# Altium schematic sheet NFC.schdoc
size 297 x 209 mm; Symbol: Drawing-Symbol_A4; @Project Name: Hưhwwuey; @Page Count: 8; @Update Date: 2026-10-18; @Create Date: 2026-10-18; @Schematic Name: Schematic1; @Page No: 8; @Page Name: P1; Company: EasyEDA.com; Version: V1.0; Page Size: A4; Device: Drawing-Symbol_A4; @Create Time: 16:45:31; @Update Time: 16:45:31; Border: 1; Width: 1170; Height: 825; Region Start: 1; X Region Count: 6; Y Region Count: 4; Blade Width: 10; Title Block Position: 3; @Board Name: Board1
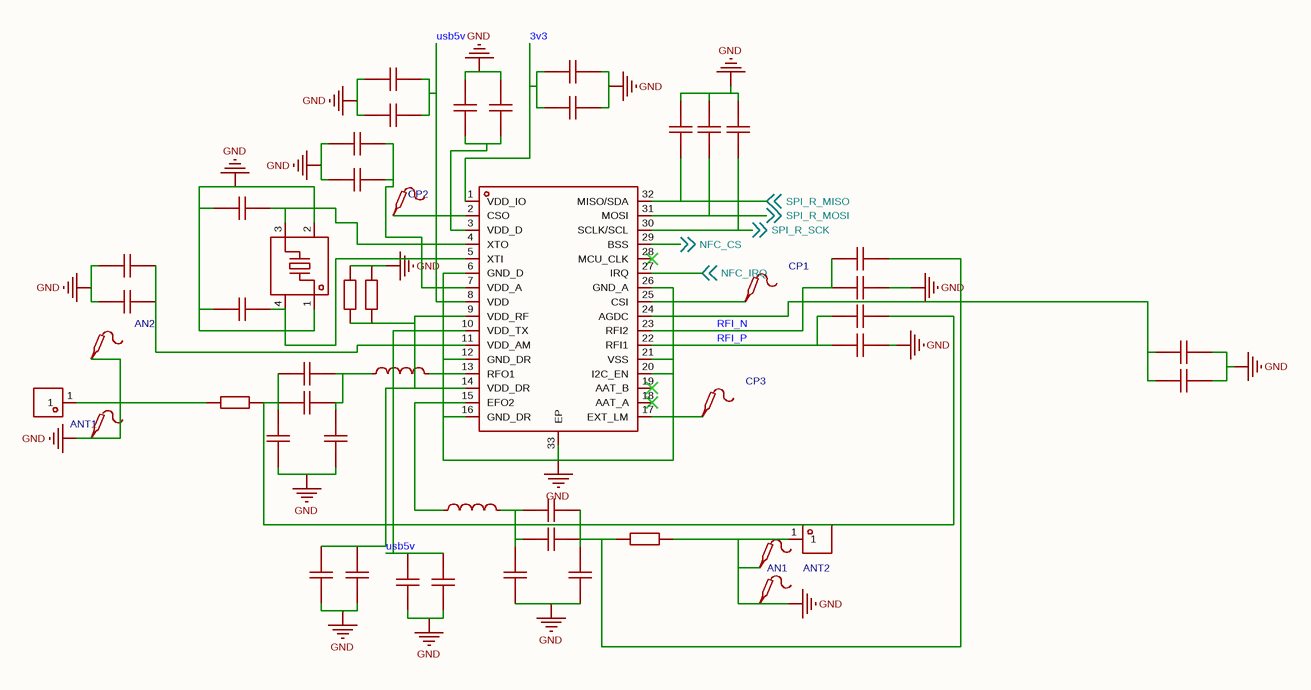
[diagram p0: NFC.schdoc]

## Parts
C91  DNP  [C0402]  (value not drawn)
C92  DNP  [C0402]  (value not drawn)
C93  DNP  [C0402]  (value not drawn)
C94  6pF  [C0402]  (value not drawn)
C95  6pF  [C0402]  (value not drawn)
C96  100pF  [C0402]  (value not drawn)
C97  10pF  [C0402]  (value not drawn)
C98  DNP  [C0402]  (value not drawn)
C99  100pF  [C0402]  (value not drawn)
C100  680pF  [C0402]  (value not drawn)
C101  62pF  [C0402]  (value not drawn)
C102  100pF  [C0402]  (value not drawn)
C103  DNP  [C0402]  (value not drawn)
C104  680pF  [C0402]  (value not drawn)
C105  62pF  [C0402]  (value not drawn)
C106  10pF  [C0402]  (value not drawn)
C107  100pF  [C0402]  (value not drawn)
C108  1uF  [C0402]  (value not drawn)
C109  10nF  [C0402]  (value not drawn)
C110  10nF  [C0402]  (value not drawn)
C111  2.2uF  [C0402]  (value not drawn)
C112  10nF  [C0402]  (value not drawn)
C113  2.2uF  [C0402]  (value not drawn)
C114  10nF  [C0402]  (value not drawn)
C115  2.2uF  [C0402]  (value not drawn)
C116  10nF  [C0402]  (value not drawn)
C117  2.2uF  [C0402]  (value not drawn)
C118  10nF  [C0402]  (value not drawn)
C119  2.2uF  [C0402]  (value not drawn)
C120  10nF  [C0402]  (value not drawn)
C121  2.2uF  [C0402]  (value not drawn)
C122  10nF  [C0402]  (value not drawn)
C123  2.2uF  [C0402]  (value not drawn)
CN4  YTC1P-3515-M20  [CONN-SMD_YTC1P-3515-M20]  (value not drawn)
CN5  YTC1P-3515-M20  [CONN-SMD_YTC1P-3515-M20]  (value not drawn)
L14  270nH  [L0201-RD]  (value not drawn)
L15  270nH  [L0201-RD]  (value not drawn)
R85  0Ω  [R0402]  (value not drawn)
R86  0Ω  [R0402]  (value not drawn)
R87  DNP  [R0402]  (value not drawn)
R88  DNP  [R0402]  (value not drawn)
TP26  CP1  [Test-Point-0.5mm]
TP27  CP2  [Test-Point-0.5mm]
TP28  AN2  [Test-Point-0.5mm]
TP29  ANT1  [Test-Point-0.5mm]
TP30  AN1  [Test-Point-0.5mm]
TP31  ANT2  [Test-Point-0.5mm]
TP32  CP3  [Test-Point-0.5mm]
U49  27.12MHz  [VFQFPN-32_L5.0-W5.0-P0.50-TL-EP3.5]  (value not drawn)
X4  27.12MHz  [CRYSTAL-SMD_4P-L2.0-W1.6-BL-B]  (value not drawn)

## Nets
GND: C91.1 C92.1 C93.1 C94.1 C95.1 C99.2 C100.1 C101.2 C104.1 C105.2 C107.2 C108.1 C109.2 C110.1 C111.1 C112.1 C113.1 C114.1 C115.1 C116.1 C117.1 C118.1 C119.1 C120.1 C121.1 C122.1 C123.1 CN4.1 CN5.1 R85.1 R86.2 R87.2 R88.2 TP28.1 TP29.1 TP30.1 TP31.1 U49.6(GND_D) U49.12(GND_DR) U49.16(GND_DR) U49.20(I2C_EN) U49.21(VSS) U49.26(GND_A) U49.33(EP) X4.1 X4.2(GND)
3v3: C122.2 C123.2 U49.1(VDD_IO)
NFC_CS: U49.29(BSS) ; off-sheet NFC_CS
NFC_IRQ: U49.27(IRQ) ; off-sheet NFC_IRQ
RFI_N: C106.2 C107.1 U49.23(RFI2)
RFI_P: C97.2 C99.1 U49.22(RFI1)
SPI_R_MISO: C93.2 U49.32(MISO/SDA) ; off-sheet SPI_R_MISO
SPI_R_MOSI: C92.2 U49.31(MOSI) ; off-sheet SPI_R_MOSI
SPI_R_SCK: C91.2 U49.30(SCLK/SCL) ; off-sheet SPI_R_SCK
usb5v: C114.2 C115.2 C116.2 C117.2 U49.8(VDD) U49.10(VDD_TX)
NetC94_2: C94.2 U49.4(XTO) X4.3
NetC95_2: C95.2 U49.5(XTI) X4.4(GND)
NetC96_1: C96.1 C97.1 C98.2 C101.1 R85.2
NetC96_2: C96.2 C98.1 C100.2 L14.1
NetC102_1: C102.1 C103.2 C104.2 L15.2
NetC102_2: C102.2 C103.1 C105.1 C106.1 R86.1
NetC108_2: C108.2 C109.1 U49.24(AGDC)
NetC110_2: C110.2 C111.2 R87.1 R88.1 U49.9(VDD_RF) U49.14(VDD_DR)
NetC112_2: C112.2 C113.2 U49.11(VDD_AM)
NetC118_2: C118.2 C119.2 U49.7(VDD_A)
NetC120_2: C120.2 C121.2 U49.3(VDD_D)
NetL14_2: L14.2 U49.13(RFO1)
NetL15_1: L15.1 U49.15(EFO2)
NetTP26_1: TP26.1 U49.25(CSI)
NetTP27_1: TP27.1 U49.2(CSO)
NetTP32_1: TP32.1 U49.17(EXT_LM)

Not connected (* = marked no-connect by the designer): U49 18(AAT_A)* 19(AAT_B)* 28(MCU_CLK)*

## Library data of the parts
C91 C98 C101 = CAP_0402: Symbol: CAP_OLD; 3D Model: b7d13df3e9464d7a99d0651d1a5b4d570819f05c4eef4c71ace90d822a990e87; 3D Model Transform: 39.37,19.685,0,0,0,0,0,0,0; Add into BOM: no; ConvertToPcb: yes; ModelName: C0402_L1.0-W0.5-H0.5
C92 C93 C103 C105 = CAP_0402: Symbol: CAP_OLD; Add into BOM: no; 3D Model: b7d13df3e9464d7a99d0651d1a5b4d570819f05c4eef4c71ace90d822a990e87; 3D Model Transform: 39.37,19.685,0,0,0,0,0,0,0; ConvertToPcb: yes; ModelName: C0402_L1.0-W0.5-H0.5
C94 C95 = GRM1555C1H6R0CA01D: Capacitance: Voltage Rated: Temperature Coefficient:; Manufacturer: muRata(村田); AddInBom: yes; ModelId: b7d13df3e9464d7a99d0651d1a5b4d570819f05c4eef4c71ace90d822a990e87; ModelName: C0402_L1.0-W0.5-H0.5; ModelTransform: 39.37,19.685,0,0,0,0,0,0,0
C96 C99 C102 C107 = CC0402JRNPO0BN101: Capacitance:100pF Tolerance:±5% Tolerance:±5% Voltage Rating:100V Temperature Coefficient:NP0; Manufacturer: YAGEO(国巨); AddInBom: yes; ModelId: b7d13df3e9464d7a99d0651d1a5b4d570819f05c4eef4c71ace90d822a990e87; ModelName: C0402_L1.0-W0.5-H0.5; ModelTransform: 39.37,19.685,0,0,0,0,0,0,0; Tolerance: ±5%; Voltage Rating: 100V; Temperature Coefficient: NP0
C97 C106 = 0402N100J500CT: Capacitance:10pF Tolerance:±5% Tolerance:±5% Voltage Rating:50V Temperature Coefficient:NP0; Manufacturer: Walsin(华新科); AddInBom: yes; ModelId: b7d13df3e9464d7a99d0651d1a5b4d570819f05c4eef4c71ace90d822a990e87; ModelName: C0402_L1.0-W0.5-H0.5; ModelTransform: 39.37,19.685,0,0,0,0,0,0,0; Tolerance: ±5%; Voltage Rating: 50V; Temperature Coefficient: NP0
C100 C104 = 0402N681J500CT: Capacitance:680pF Tolerance:±5% Tolerance:±5% Voltage Rating:50V Temperature Coefficient:NP0; Manufacturer: Walsin(华新科); AddInBom: yes; ModelId: b7d13df3e9464d7a99d0651d1a5b4d570819f05c4eef4c71ace90d822a990e87; ModelName: C0402_L1.0-W0.5-H0.5; ModelTransform: 39.37,19.685,0,0,0,0,0,0,0; Tolerance: ±5%; Voltage Rating: 50V; Temperature Coefficient: NP0
C108 = TCC0402X5R105M6R3AT: Capacitance:1uF Tolerance:±20% Tolerance:±20% Voltage Rating:6.3V Temperature Coefficient:X5R; Manufacturer: CCTC(三环); AddInBom: yes; ModelId: b7d13df3e9464d7a99d0651d1a5b4d570819f05c4eef4c71ace90d822a990e87; ModelName: C0402_L1.0-W0.5-H0.5; ModelTransform: 39.37,19.685,0,0,0,0,0,0,0; Tolerance: ±20%; Voltage Rating: 6.3V; Temperature Coefficient: X5R
C109 C110 C112 C114 = FCC0402B103K500AT: Capacitance:10nF Tolerance:±10% Tolerance:±10% Voltage Rating:50V Temperature Coefficient:X7R Operating Temperature:-55℃~+125℃ Operating Temperature:-55℃~+125℃; Manufacturer: FOJAN(富捷); AddInBom: yes; ModelId: b7d13df3e9464d7a99d0651d1a5b4d570819f05c4eef4c71ace90d822a990e87; ModelName: C0402_L1.0-W0.5-H0.5; ModelTransform: 39.37,19.685,0,0,0,0,0,0,0; Tolerance: ±10%; Voltage Rating: 50V; Temperature Coefficient: X7R
C111 C113 C115 C117 C119 C121 C123 = CL05A225MQ5NSNC: Capacitance:2.2uF Tolerance:±20% Tolerance:±20% Voltage Rating:6.3V Temperature Coefficient:X5R; Manufacturer: SAMSUNG(三星); 3D Model: b7d13df3e9464d7a99d0651d1a5b4d570819f05c4eef4c71ace90d822a990e87; 3D Model Transform: 39.37,19.685,0,0,0,0,0,0,0; Tolerance: ±20%; Voltage Rating: 6.3V; Temperature Coefficient: X5R; AddInBom: yes; ModelName: C0402_L1.0-W0.5-H0.5
C116 C118 C120 C122 = FCC0402B103K500AT: Capacitance:10nF Tolerance:±10% Tolerance:±10% Voltage Rating:50V Temperature Coefficient:X7R Operating Temperature:-55℃~+125℃ Operating Temperature:-55℃~+125℃; Manufacturer: FOJAN(富捷); 3D Model: b7d13df3e9464d7a99d0651d1a5b4d570819f05c4eef4c71ace90d822a990e87; 3D Model Transform: 39.37,19.685,0,0,0,0,0,0,0; Tolerance: ±10%; Voltage Rating: 50V; Temperature Coefficient: X7R; AddInBom: yes; ModelName: C0402_L1.0-W0.5-H0.5
CN4 CN5 = YTC1P-3515-M20: Type:Pogo Pin Number of Pins:1P Overall Length/Height:4mm Contact Material:Brass Contact Plating:Gold; Manufacturer: YIYUAN(怡远); AddInBom: yes; ModelId: e956e29c821d4094900f1c4d8f713bf40819f05c4eef4c71ace90d822a990e87; ModelTransform: 78.624,78.682,0,0,0,0,0,0,0; Overall Length/Height: 4mm
L14 L15 = LQP03TNR27H02D: Inductance: Tolerance:±3% Tolerance:±3% Rated Current: Saturation Current (Isat):- DC Resistance (DCR): Q @ Freq:5@100MHz Frequency - Self Resonant:450MHz Ratings:; Manufacturer: muRata(村田); AddInBom: yes; ModelId: d887176703ad44ad84b18f9ed82e768d0819f05c4eef4c71ace90d822a990e87; ModelTransform: 23.622,11.811,0,0,0,0,0,0,0; Tolerance: ±3%; Frequency - Self Resonant: 450MHz
R85 R86 = WR04X000PTL: Type:Thick Film Resistor Resistance:0Ω Tolerance:- Tolerance:- Power(Watts):62.5mW Voltage-Supply(Max):50V Temperature Coefficient:-200ppm/℃~+400ppm/℃ Temperature Coefficient:-200ppm/℃~+400ppm/℃ Operating Temperature:-55℃~+155℃ Operating Temperature:-55℃~; Manufacturer: Walsin(华新科); 3D Model: efdecb7dae4442949d28eecaf748420f0819f05c4eef4c71ace90d822a990e87; 3D Model Transform: 39.37,19.685,0,0,0,0,0,0,0; Power(Watts): 62.5mW; Voltage-Supply(Max): 50V; AddInBom: yes; ModelName: R0402_L1.0-W0.5-H0.4
R87 R88 = Res_0402: Symbol: Res; 3D Model: efdecb7dae4442949d28eecaf748420f0819f05c4eef4c71ace90d822a990e87; 3D Model Transform: 39.37,19.685,0,0,0,0,0,0,0; Add into BOM: no; ConvertToPcb: yes; ModelName: R0402_L1.0-W0.5-H0.4
TP26-TP32 = Test-Point: Test Point 测试点; AddInBom: yes
U49 = ST25R3916-AQWT_C2908147: agreement:FeliCa,ISO 14443A,ISO 14443B,ISO 15693,MIFARE,NFC Interface:I2C,SPI transmission rate:53Kbit/s；848Kbit/s；424Kbit/s Frequency:27.12MHz Frequency:27.12MHz Voltage - Supply:2.4V~5.5V Voltage - Supply:2.4V~5.5V Quiescent Current:- Features:Built-in; Manufacturer: ST(意法半导体); AddInBom: yes; ModelId: aa3209b0cc65446da375377f1d83c4730819f05c4eef4c71ace90d822a990e87; ModelTransform: 197.6374,197.6374,0,0,0,0,0.005,0,0
X4 = XRCGB27M120F3M00R0: Frequency:27.12MHz Voltage - Supply:- Voltage - Supply:- Current - Supply:- Programmable:No Operating Temperature:-30℃~+85℃ Operating Temperature:-30℃~+85℃ Timer Number:- Time Intervals:- Time Intervals:- Features:-; Manufacturer: muRata(村田); AddInBom: yes; ModelId: 5de808a48c6e4dc7933aafd5de6f241f0819f05c4eef4c71ace90d822a990e87; ModelTransform: 79.1337,62.992,0,0,0,0,0,0,0; Programmable: No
